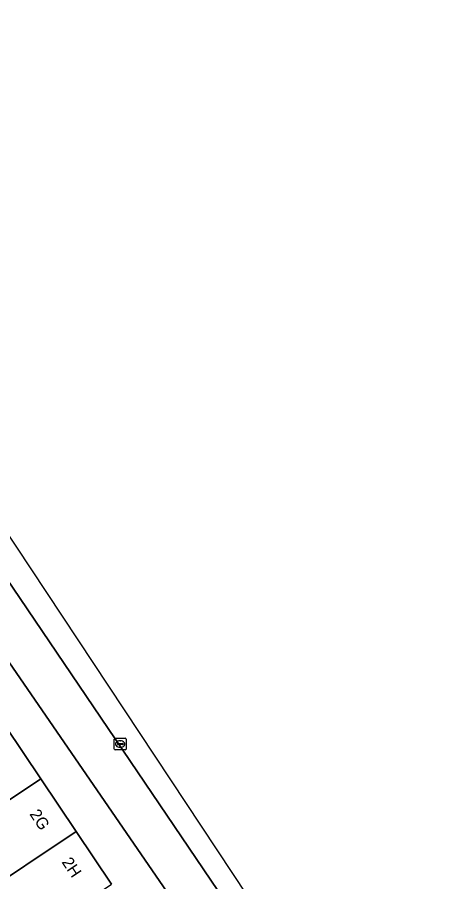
# Model space of a CAD drawing. Extents: x 158352 to 159489, y 383828 to 384603.
# Drawn here: x 158828.8 to 158865.5, y 384521.3 to 384594.9 of the extents above; entities that cross this region are included whole.
import ezdxf

# ---------------------------------------------------------------- set-up
doc = ezdxf.new("R2010")
doc.units = 0
for name, color, linetype in [('IMGEO_Groenvoorziening', 7, 'Continuous'), ('IMGEO_Kolk', 7, 'Continuous'), ('IMGEO_Pand', 7, 'Continuous'), ('IMGEO_Pand_nummerreeks', 7, 'Continuous'), ('IMGEO_Rijbaan_lokaal_open', 7, 'Continuous'), ('IMGEO_Voetpad_open', 7, 'Continuous')]:
    doc.layers.add(name, color=color, linetype=linetype)

msp = doc.modelspace()

# ---------------------------------------------------------------- linework, layer by layer
at = {"layer": 'IMGEO_Groenvoorziening'}
for points in [[(158846.175, 384513.696), (158791.916, 384592.555), (158698.254, 384508.831)], [(158827.79, 384534.554), (158830.799, 384530.07), (158833.807, 384525.585), (158836.816, 384521.101)]]:
    msp.add_lwpolyline(points, dxfattribs=at)
at = {"layer": 'IMGEO_Kolk'}
for p, q in [((158837.056, 384532.598), (158837.056, 384533.45)), ((158837.131, 384533.524), (158837.983, 384533.524)), ((158837.358, 384533.067), (158837.756, 384533.067)), ((158837.544, 384533.304), (158837.569, 384533.304)), ((158838.057, 384533.45), (158838.057, 384532.598)), ((158837.983, 384532.524), (158837.131, 384532.524)), ((158837.315, 384533.018), (158837.315, 384533.03)), ((158837.753, 384532.981), (158837.355, 384532.981)), ((158837.567, 384532.744), (158837.542, 384532.744)), ((158837.799, 384533.03), (158837.799, 384533.018))]:
    msp.add_line(p, q, dxfattribs=at)
for points in [[(158837.056, 384532.598), (158837.056, 384533.45)], [(158837.131, 384533.524), (158837.983, 384533.524)], [(158838.057, 384533.45), (158838.057, 384532.598)], [(158837.983, 384532.524), (158837.131, 384532.524)]]:
    msp.add_lwpolyline(points, dxfattribs=at)
for centre, radius, start, end in [((158837.133, 384533.448), 0.0765, 91.55205, 178.44795), ((158837.133, 384533.448), 0.0765, 91.55205, 178.44795), ((158837.355, 384533.027), 0.0403, 85.87752, 175.75265), ((158837.76, 384533.029), 0.0386, 1.73085, 96.63898), ((158837.981, 384533.448), 0.0765, 1.55205, 88.44795), ((158837.981, 384533.448), 0.0765, 1.55205, 88.44795), ((158837.133, 384532.6), 0.0765, 181.55205, 268.44795), ((158837.133, 384532.6), 0.0765, 181.55205, 268.44795), ((158837.352, 384533.017), 0.0366, 178.93798, 274.71019), ((158837.756, 384533.024), 0.043, 264.86636, 352.45326), ((158837.981, 384532.6), 0.0765, 271.55205, 358.44795), ((158837.981, 384532.6), 0.0765, 271.55205, 358.44795)]:
    msp.add_arc(centre, radius, start, end, dxfattribs=at)
for centre, major_axis, ratio, start_param, end_param in [((158837.543, 384533.024), (-0.387, 0.002), 0.722429, 4.712389, 7.853982), ((158837.568, 384533.024), (-0.39, 0.002), 0.717154, 1.570796, 4.712389)]:
    msp.add_ellipse(centre, major_axis=major_axis, ratio=ratio, start_param=start_param, end_param=end_param, dxfattribs=at)
at = {"layer": 'IMGEO_Pand'}
for points in [[(158830.799, 384530.07), (158827.79, 384534.554), (158819.131, 384528.761), (158819.288, 384528.527), (158822.135, 384524.274)], [(158833.807, 384525.585), (158830.799, 384530.07), (158822.135, 384524.274), (158825.138, 384519.787)], [(158836.816, 384521.101), (158833.807, 384525.585), (158825.138, 384519.787), (158827.989, 384515.528), (158828.143, 384515.299)]]:
    msp.add_lwpolyline(points, close=True, dxfattribs=at)
at = {"layer": 'IMGEO_Rijbaan_lokaal_open'}
msp.add_lwpolyline([(158865.509, 384494.258), (158799.754, 384593.551), (158797.471, 384591.965), (158820.926, 384557.346), (158853.346, 384509.504), (158863.389, 384494.566), (158863.855, 384493.983)], dxfattribs=at)
at = {"layer": 'IMGEO_Voetpad_open'}
for points in [[(158820.926, 384557.346), (158797.471, 384591.965), (158796.669, 384593.149), (158795.466, 384594.855), (158793.559, 384594.024), (158791.916, 384592.555), (158846.175, 384513.696), (158849.3, 384509.154), (158863.532, 384488.47), (158863.954, 384485.975)], [(158863.855, 384493.983), (158863.389, 384494.566), (158853.346, 384509.504), (158820.926, 384557.346)]]:
    msp.add_lwpolyline(points, dxfattribs=at)

# ---------------------------------------------------------------- texts
at = {"layer": 'IMGEO_Pand_nummerreeks'}
for s, p in [('2G', (158829.805, 384527.063)), ('2H', (158832.545, 384522.979))]:
    msp.add_text(s, height=1, rotation=303.85587, dxfattribs=at).set_placement(p)

doc.saveas('drawing.dxf')
